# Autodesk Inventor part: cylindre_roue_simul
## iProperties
Created: 2011-01
Part Number: cylindre_roue_simul
Document SubType Name: Modeling
Designer: eric
Density: 1 g/cm^3
Mass: 1188.48 g
Surface Area: 1706.83 cm^2
Volume: 1188.48 cm^3
Author: eric
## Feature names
1. Extrusion1
